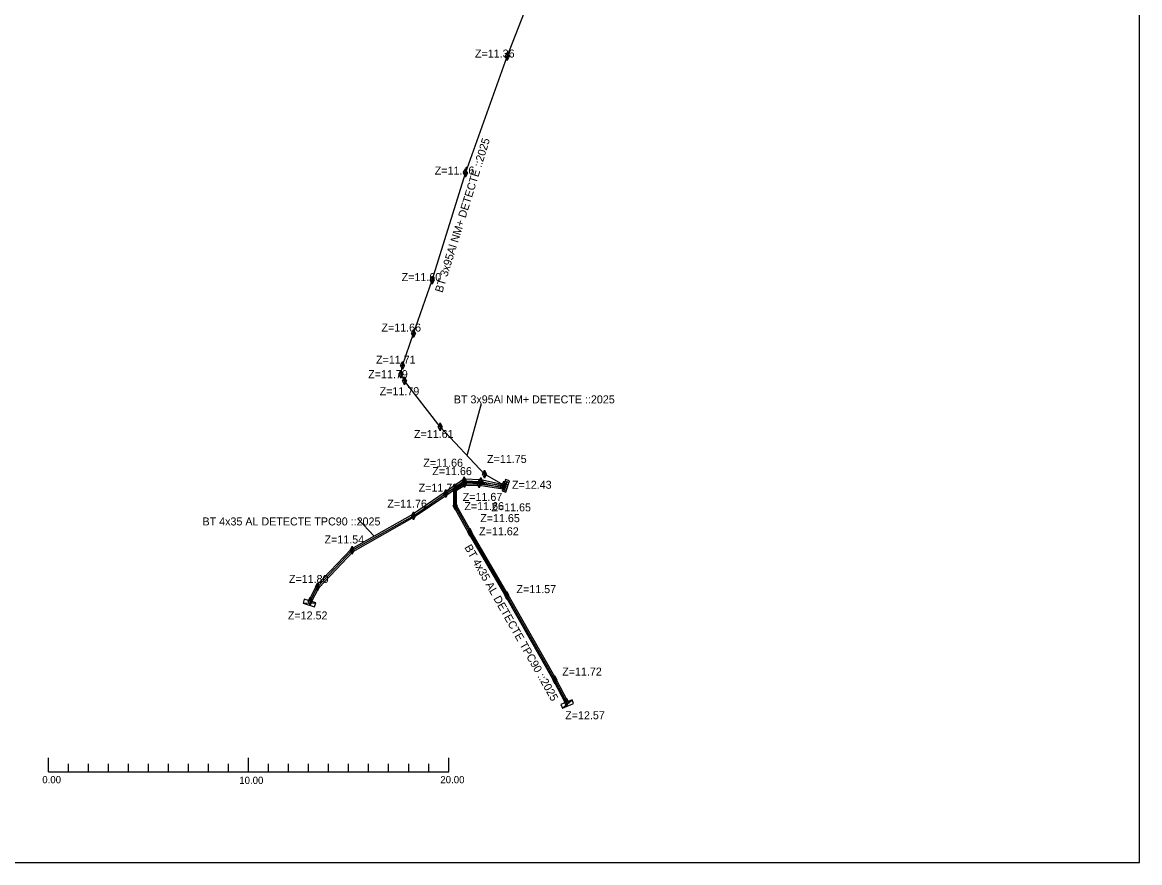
# Model space of a CAD drawing. Extents: x 376946 to 377047, y 296637 to 296721.
# Drawn here: x 376991.3 to 377047.1, y 296637.1 to 296679.1 of the extents above; entities that cross this region are included whole.
import ezdxf

# ---------------------------------------------------------------- set-up
doc = ezdxf.new("R2010")
doc.units = 0
for name, color, linetype in [('EncartsIndif', 7, 'Continuous'), ('PGOC_BRCHT_LR_CONSTRUIT', 7, 'Continuous'), ('PGOC_BT_CONSTRUIT', 7, 'Continuous'), ('PGOC_HABILLAGE_PGOC', 7, 'Continuous'), ('PGOC_PROTECTION_MECANIQUE', 7, 'Continuous'), ('PGOC_PTRL', 7, 'Continuous'), ('Plan_Cartouches', 7, 'Continuous')]:
    doc.layers.add(name, color=color, linetype=linetype)

msp = doc.modelspace()

# ---------------------------------------------------------------- linework, layer by layer
at = {"layer": 'EncartsIndif'}
for points in [[(377013.497, 296657.455), (377014.217, 296660.063)], [(377008.846, 296653.427), (377008.03, 296654.289)]]:
    msp.add_lwpolyline(points, dxfattribs=at)
at = {"layer": 'PGOC_BRCHT_LR_CONSTRUIT'}
for points in [[(377005.642, 296650.181), (377006.017, 296650.893), (377007.746, 296652.72), (377010.805, 296654.448), (377012.433, 296655.555), (377013.351, 296656.197), (377014.172, 296656.159), (377015.31, 296655.917)], [(377018.454, 296645.132), (377017.87, 296646.242), (377015.481, 296650.461), (377013.63, 296653.619), (377012.888, 296654.942), (377012.886, 296655.759), (377013.359, 296656.056), (377014.099, 296656.047), (377015.316, 296655.87)]]:
    msp.add_lwpolyline(points, dxfattribs=at)
at = {"layer": 'PGOC_BT_CONSTRUIT'}
for p, q in [((377005.296, 296650.081), (377005.928, 296650.091)), ((377018.256, 296644.831), (377018.731, 296645.249))]:
    msp.add_line(p, q, dxfattribs=at)
for points in [[(377015.327, 296655.971), (377014.364, 296656.533), (377012.15, 296658.888), (377010.355, 296661.19), (377010.173, 296661.529), (377010.27, 296661.958), (377010.808, 296663.561), (377011.751, 296666.226), (377013.407, 296671.561), (377015.487, 296677.397), (377017.901, 296683.591), (377020.143, 296689.776), (377022.225, 296696.206), (377024.682, 296702.64), (377026.423, 296707.991), (377027.756, 296711.46), (377029.162, 296713.33), (377029.778, 296713.834)], [(377015.346, 296655.693), (377015.499, 296656.19)], [(377015.375, 296656.061), (377015.528, 296656.013)], [(377015.405, 296656.156), (377015.558, 296656.109)], [(377015.287, 296655.774), (377015.44, 296655.727)], [(377015.316, 296655.87), (377015.469, 296655.822)], [(377015.346, 296655.965), (377015.499, 296655.918)]]:
    msp.add_lwpolyline(points, dxfattribs=at)
for points in [[(377015.415, 296656.258), (377015.238, 296655.684), (377015.429, 296655.625), (377015.606, 296656.199)], [(377005.928, 296650.091), (377005.356, 296650.272), (377005.296, 296650.081), (377005.868, 296649.9)], [(377018.731, 296645.249), (377018.178, 296645.015), (377018.256, 296644.831), (377018.809, 296645.065)]]:
    msp.add_lwpolyline(points, close=True, dxfattribs=at)
at = {"layer": 'PGOC_HABILLAGE_PGOC'}
msp.add_lwpolyline([(376987.689, 296721.108), (376987.689, 296637.108), (377047.089, 296637.108), (377047.089, 296721.108)], close=True, dxfattribs=at)
at = {"layer": 'PGOC_PROTECTION_MECANIQUE'}
for points in [[(377015.313, 296655.993), (377014.182, 296656.234), (377013.329, 296656.273), (377012.391, 296655.617), (377010.765, 296654.512), (377007.699, 296652.779), (377005.956, 296650.937), (377005.576, 296650.216)], [(377005.709, 296650.146), (377006.079, 296650.849), (377007.793, 296652.66), (377010.845, 296654.385), (377012.476, 296655.494), (377013.373, 296656.121), (377014.163, 296656.084), (377015.282, 296655.846)], [(377015.301, 296655.948), (377014.105, 296656.122), (377013.337, 296656.131), (377012.811, 296655.8), (377012.813, 296654.922), (377013.565, 296653.582), (377015.416, 296650.424), (377017.804, 296646.206), (377018.388, 296645.097)], [(377018.521, 296645.167), (377017.936, 296646.278), (377015.546, 296650.499), (377013.695, 296653.656), (377012.963, 296654.962), (377012.961, 296655.717), (377013.38, 296655.98), (377014.094, 296655.972), (377015.28, 296655.799)], [(377015.28, 296655.799), (377015.301, 296655.948)], [(377015.282, 296655.846), (377015.313, 296655.993)], [(377005.576, 296650.216), (377005.709, 296650.146)], [(377018.388, 296645.097), (377018.521, 296645.167)]]:
    msp.add_lwpolyline(points, dxfattribs=at)
at = {"layer": 'PGOC_PTRL'}
for points in [[(377015.387, 296677.397), (377015.487, 296677.597), (377015.587, 296677.397), (377015.487, 296677.197), (377015.387, 296677.397)], [(377015.587, 296677.397), (377015.487, 296677.397), (377015.387, 296677.397)], [(377015.487, 296677.597), (377015.487, 296677.197)], [(377013.307, 296671.561), (377013.407, 296671.761), (377013.507, 296671.561), (377013.407, 296671.361), (377013.307, 296671.561)], [(377013.407, 296671.761), (377013.407, 296671.361)], [(377013.507, 296671.561), (377013.407, 296671.561), (377013.307, 296671.561)], [(377011.651, 296666.226), (377011.751, 296666.426), (377011.851, 296666.226), (377011.751, 296666.026), (377011.651, 296666.226)], [(377011.851, 296666.226), (377011.751, 296666.226), (377011.651, 296666.226)], [(377011.751, 296666.426), (377011.751, 296666.026)], [(377010.708, 296663.561), (377010.808, 296663.761), (377010.908, 296663.561), (377010.808, 296663.361), (377010.708, 296663.561)], [(377010.908, 296663.561), (377010.808, 296663.561), (377010.708, 296663.561)], [(377010.808, 296663.761), (377010.808, 296663.361)], [(377010.073, 296661.529), (377010.173, 296661.729), (377010.273, 296661.529), (377010.173, 296661.329), (377010.073, 296661.529)], [(377010.17, 296661.958), (377010.27, 296662.158), (377010.37, 296661.958), (377010.27, 296661.758), (377010.17, 296661.958)], [(377010.37, 296661.958), (377010.27, 296661.958), (377010.17, 296661.958)], [(377010.173, 296661.729), (377010.173, 296661.329)], [(377010.27, 296662.158), (377010.27, 296661.758)], [(377010.273, 296661.529), (377010.173, 296661.529), (377010.073, 296661.529)], [(377010.255, 296661.19), (377010.355, 296661.39), (377010.455, 296661.19), (377010.355, 296660.99), (377010.255, 296661.19)], [(377010.455, 296661.19), (377010.355, 296661.19), (377010.255, 296661.19)], [(377010.355, 296661.39), (377010.355, 296660.99)], [(377012.05, 296658.888), (377012.15, 296659.088), (377012.25, 296658.888), (377012.15, 296658.688), (377012.05, 296658.888)], [(377012.25, 296658.888), (377012.15, 296658.888), (377012.05, 296658.888)], [(377012.15, 296659.088), (377012.15, 296658.688)], [(377014.264, 296656.533), (377014.364, 296656.733), (377014.464, 296656.533), (377014.364, 296656.333), (377014.264, 296656.533)], [(377014.364, 296656.733), (377014.364, 296656.333)], [(377013.251, 296656.197), (377013.351, 296656.397), (377013.451, 296656.197), (377013.351, 296655.997), (377013.251, 296656.197)], [(377013.451, 296656.197), (377013.351, 296656.197), (377013.251, 296656.197)], [(377013.259, 296656.056), (377013.359, 296656.256), (377013.459, 296656.056), (377013.359, 296655.856), (377013.259, 296656.056)], [(377013.459, 296656.056), (377013.359, 296656.056), (377013.259, 296656.056)], [(377013.351, 296656.397), (377013.351, 296655.997)], [(377013.359, 296656.256), (377013.359, 296655.856)], [(377013.999, 296656.047), (377014.099, 296656.247), (377014.199, 296656.047), (377014.099, 296655.847), (377013.999, 296656.047)], [(377014.199, 296656.047), (377014.099, 296656.047), (377013.999, 296656.047)], [(377014.072, 296656.159), (377014.172, 296656.359), (377014.272, 296656.159), (377014.172, 296655.959), (377014.072, 296656.159)], [(377014.272, 296656.159), (377014.172, 296656.159), (377014.072, 296656.159)], [(377014.099, 296656.247), (377014.099, 296655.847)], [(377014.172, 296656.359), (377014.172, 296655.959)], [(377014.464, 296656.533), (377014.364, 296656.533), (377014.264, 296656.533)], [(377015.227, 296655.971), (377015.327, 296656.171), (377015.427, 296655.971), (377015.327, 296655.771), (377015.227, 296655.971)], [(377015.327, 296656.171), (377015.327, 296655.771)], [(377012.333, 296655.555), (377012.433, 296655.755), (377012.533, 296655.555), (377012.433, 296655.355), (377012.333, 296655.555)], [(377012.533, 296655.555), (377012.433, 296655.555), (377012.333, 296655.555)], [(377012.433, 296655.755), (377012.433, 296655.355)], [(377012.786, 296655.759), (377012.886, 296655.959), (377012.986, 296655.759), (377012.886, 296655.559), (377012.786, 296655.759)], [(377012.986, 296655.759), (377012.886, 296655.759), (377012.786, 296655.759)], [(377012.886, 296655.959), (377012.886, 296655.559)], [(377015.427, 296655.971), (377015.327, 296655.971), (377015.227, 296655.971)], [(377012.788, 296654.942), (377012.888, 296655.142), (377012.988, 296654.942), (377012.888, 296654.742), (377012.788, 296654.942)], [(377012.988, 296654.942), (377012.888, 296654.942), (377012.788, 296654.942)], [(377012.888, 296655.142), (377012.888, 296654.742)], [(377010.705, 296654.448), (377010.805, 296654.648), (377010.905, 296654.448), (377010.805, 296654.248), (377010.705, 296654.448)], [(377010.905, 296654.448), (377010.805, 296654.448), (377010.705, 296654.448)], [(377010.805, 296654.648), (377010.805, 296654.248)], [(377013.53, 296653.619), (377013.63, 296653.819), (377013.73, 296653.619), (377013.63, 296653.419), (377013.53, 296653.619)], [(377013.63, 296653.819), (377013.63, 296653.419)], [(377013.73, 296653.619), (377013.63, 296653.619), (377013.53, 296653.619)], [(377007.646, 296652.72), (377007.746, 296652.92), (377007.846, 296652.72), (377007.746, 296652.52), (377007.646, 296652.72)], [(377007.846, 296652.72), (377007.746, 296652.72), (377007.646, 296652.72)], [(377007.746, 296652.92), (377007.746, 296652.52)], [(377005.917, 296650.893), (377006.017, 296651.093), (377006.117, 296650.893), (377006.017, 296650.693), (377005.917, 296650.893)], [(377006.017, 296651.093), (377006.017, 296650.693)], [(377006.117, 296650.893), (377006.017, 296650.893), (377005.917, 296650.893)], [(377015.381, 296650.461), (377015.481, 296650.661), (377015.581, 296650.461), (377015.481, 296650.261), (377015.381, 296650.461)], [(377015.581, 296650.461), (377015.481, 296650.461), (377015.381, 296650.461)], [(377015.481, 296650.661), (377015.481, 296650.261)], [(377005.542, 296650.181), (377005.642, 296650.381), (377005.742, 296650.181), (377005.642, 296649.981), (377005.542, 296650.181)], [(377005.742, 296650.181), (377005.642, 296650.181), (377005.542, 296650.181)], [(377005.642, 296650.381), (377005.642, 296649.981)], [(377017.77, 296646.242), (377017.87, 296646.442), (377017.97, 296646.242), (377017.87, 296646.042), (377017.77, 296646.242)], [(377017.97, 296646.242), (377017.87, 296646.242), (377017.77, 296646.242)], [(377017.87, 296646.442), (377017.87, 296646.042)], [(377018.354, 296645.132), (377018.454, 296645.332), (377018.554, 296645.132), (377018.454, 296644.932), (377018.354, 296645.132)], [(377018.554, 296645.132), (377018.454, 296645.132), (377018.354, 296645.132)], [(377018.454, 296645.332), (377018.454, 296644.932)]]:
    msp.add_lwpolyline(points, dxfattribs=at)
at = {"layer": 'Plan_Cartouches'}
for p, q in [((376992.571, 296641.64), (376992.571, 296642.34)), ((377002.571, 296641.64), (377002.571, 296642.34)), ((377012.571, 296641.64), (377012.571, 296642.34)), ((376992.571, 296641.64), (377012.571, 296641.64)), ((376993.571, 296641.64), (376993.571, 296642.04)), ((376994.571, 296641.64), (376994.571, 296642.04)), ((376995.571, 296641.64), (376995.571, 296642.04)), ((376996.571, 296641.64), (376996.571, 296642.04)), ((376997.571, 296641.64), (376997.571, 296642.04)), ((376998.571, 296641.64), (376998.571, 296642.04)), ((376999.571, 296641.64), (376999.571, 296642.04)), ((377000.571, 296641.64), (377000.571, 296642.04)), ((377001.571, 296641.64), (377001.571, 296642.04)), ((377003.571, 296641.64), (377003.571, 296642.04)), ((377004.571, 296641.64), (377004.571, 296642.04)), ((377005.571, 296641.64), (377005.571, 296642.04)), ((377006.571, 296641.64), (377006.571, 296642.04)), ((377007.571, 296641.64), (377007.571, 296642.04)), ((377008.571, 296641.64), (377008.571, 296642.04)), ((377009.571, 296641.64), (377009.571, 296642.04)), ((377010.571, 296641.64), (377010.571, 296642.04)), ((377011.571, 296641.64), (377011.571, 296642.04))]:
    msp.add_line(p, q, dxfattribs=at)

# ---------------------------------------------------------------- texts
at = {"layer": 'PGOC_BRCHT_LR_CONSTRUIT'}
msp.add_text('BT 4x35 AL DETECTE TPC90 ::2025', height=0.4, dxfattribs=at).set_placement((377000.271, 296653.962))
msp.add_text('BT 4x35 AL DETECTE TPC90 ::2025', height=0.4, rotation=299.5141, dxfattribs=at).set_placement((377013.341, 296652.871))
at = {"layer": 'PGOC_BT_CONSTRUIT'}
msp.add_text('BT 3x95Al NM+ DETECTE ::2025', height=0.4, rotation=72.7527, dxfattribs=at).set_placement((377012.253, 296665.57))
msp.add_text('BT 3x95Al NM+ DETECTE ::2025', height=0.4, dxfattribs=at).set_placement((377012.825, 296660.063))
at = {"layer": 'PGOC_PTRL'}
for s, p in [('Z=11.36', (377013.883, 296677.347)), ('Z=11.46', (377011.874, 296671.501)), ('Z=11.60', (377010.22, 296666.176)), ('Z=11.66', (377009.211, 296663.65)), ('Z=11.71', (377008.941, 296662.047)), ('Z=11.79', (377008.549, 296661.323)), ('Z=11.79', (377009.121, 296660.472)), ('Z=11.61', (377010.837, 296658.331)), ('Z=11.66', (377011.306, 296656.895)), ('Z=11.75', (377014.487, 296657.085)), ('Z=11.66', (377011.749, 296656.477)), ('Z=11.73', (377011.068, 296655.649)), ('Z=12.43', (377015.734, 296655.796)), ('Z=11.67', (377013.271, 296655.189)), ('Z=11.76', (377009.503, 296654.85)), ('Z=11.66', (377013.354, 296654.727)), ('Z=11.65', (377014.702, 296654.666)), ('Z=11.65', (377014.145, 296654.126)), ('Z=11.62', (377014.091, 296653.47)), ('Z=11.54', (377006.367, 296653.061)), ('Z=11.80', (377004.589, 296651.088)), ('Z=11.57', (377015.957, 296650.578)), ('Z=12.52', (377004.536, 296649.265)), ('Z=11.72', (377018.241, 296646.458)), ('Z=12.57', (377018.39, 296644.274))]:
    msp.add_text(s, height=0.4, dxfattribs=at).set_placement(p)
at = {"layer": 'Plan_Cartouches'}
for s, p in [('0.00', (376992.266, 296641.076)), ('10.00', (377002.107, 296641.042)), ('20.00', (377012.153, 296641.076))]:
    msp.add_text(s, height=0.36, dxfattribs=at).set_placement(p)

doc.saveas('drawing.dxf')
